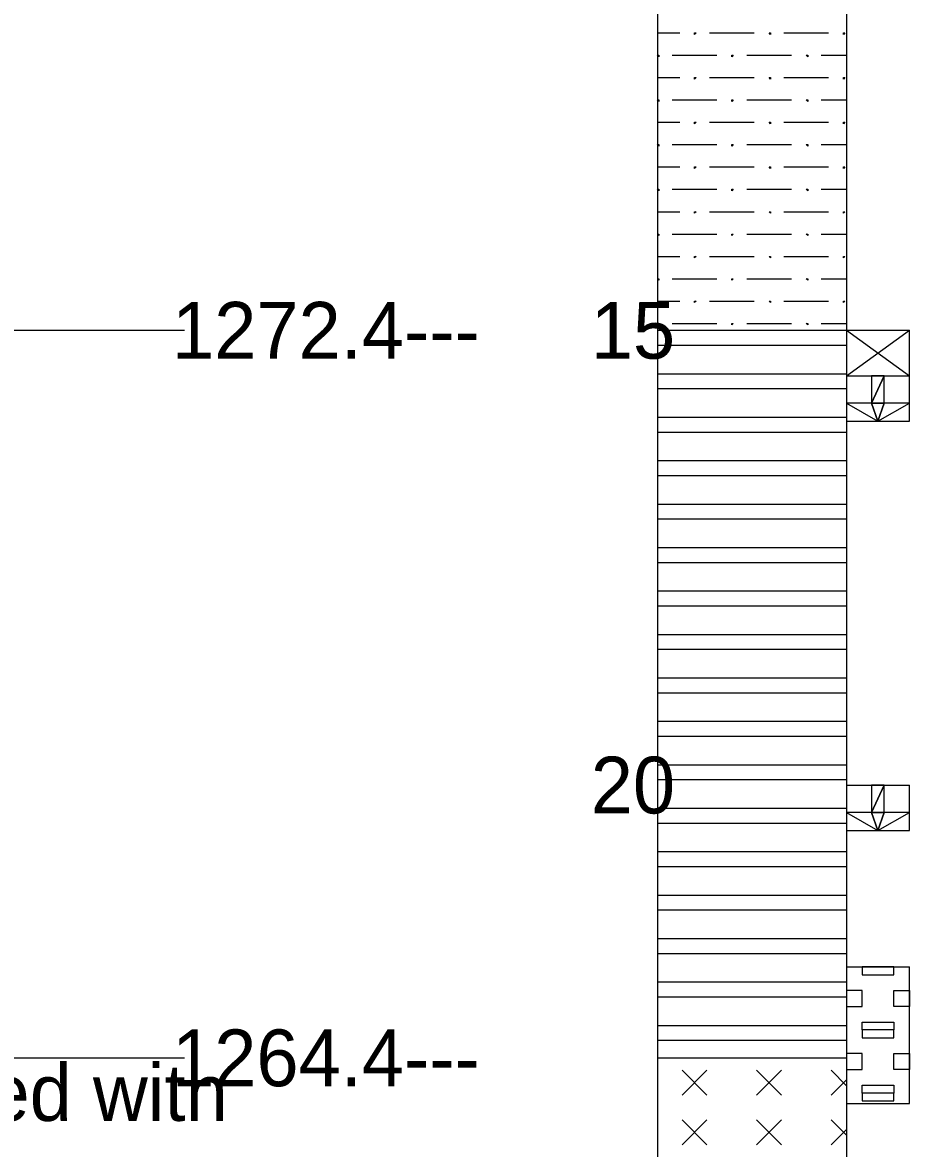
# Model space of a CAD drawing. Extents: x 2150148.6 to 2150220.1, y 143803.7 to 143875.1.
# Drawn here: x 2150200.808 to 2150203.153, y 143852.692 to 143855.669 of the extents above; entities that cross this region are included whole.
import ezdxf

# ---------------------------------------------------------------- set-up
doc = ezdxf.new("R2010")
doc.units = 0
doc.layers.add('Default', color=7, linetype='Continuous')

msp = doc.modelspace()

# ---------------------------------------------------------------- linework, layer by layer
at = {"layer": 'Default'}
for points in [[(2150202.4866, 143858.3678), (2150202.4866, 143846.4416)], [(2150202.9866, 143858.3606), (2150202.9866, 143846.4416)], [(2150202.4866, 143855.6411), (2150202.5456, 143855.6411)], [(2150202.585, 143855.6411), (2150202.5889, 143855.6411), (2150202.585, 143855.6372), (2150202.585, 143855.6411)], [(2150202.6244, 143855.6411), (2150202.7425, 143855.6411)], [(2150202.7818, 143855.6411), (2150202.7858, 143855.6411), (2150202.7858, 143855.6372), (2150202.7818, 143855.6411)], [(2150202.8212, 143855.6411), (2150202.8803, 143855.6411)], [(2150202.8803, 143855.6411), (2150202.9393, 143855.6411)], [(2150202.9787, 143855.6411), (2150202.9826, 143855.6411), (2150202.9787, 143855.6372), (2150202.9787, 143855.6411)], [(2150202.4866, 143855.5821), (2150202.4905, 143855.5821), (2150202.4905, 143855.5781), (2150202.4866, 143855.5821)], [(2150202.5259, 143855.5821), (2150202.644, 143855.5821)], [(2150202.6834, 143855.5821), (2150202.6874, 143855.5821), (2150202.6834, 143855.5781), (2150202.6834, 143855.5821)], [(2150202.7228, 143855.5821), (2150202.8409, 143855.5821)], [(2150202.8803, 143855.5821), (2150202.8842, 143855.5821), (2150202.8842, 143855.5781), (2150202.8803, 143855.5821)], [(2150202.9196, 143855.5821), (2150202.9866, 143855.5821)], [(2150202.4866, 143855.523), (2150202.5456, 143855.523)], [(2150202.585, 143855.523), (2150202.5889, 143855.523), (2150202.585, 143855.5191), (2150202.585, 143855.523)], [(2150202.6244, 143855.523), (2150202.7425, 143855.523)], [(2150202.7818, 143855.523), (2150202.7858, 143855.523), (2150202.7858, 143855.5191), (2150202.7818, 143855.523)], [(2150202.8212, 143855.523), (2150202.8803, 143855.523)], [(2150202.8803, 143855.523), (2150202.9393, 143855.523)], [(2150202.9787, 143855.523), (2150202.9826, 143855.523), (2150202.9787, 143855.5191), (2150202.9787, 143855.523)], [(2150202.4866, 143855.464), (2150202.4905, 143855.464), (2150202.4905, 143855.46), (2150202.4866, 143855.464)], [(2150202.5259, 143855.464), (2150202.644, 143855.464)], [(2150202.6834, 143855.464), (2150202.6874, 143855.464), (2150202.6834, 143855.46), (2150202.6834, 143855.464)], [(2150202.7228, 143855.464), (2150202.8409, 143855.464)], [(2150202.8803, 143855.464), (2150202.8842, 143855.464), (2150202.8842, 143855.46), (2150202.8803, 143855.464)], [(2150202.9196, 143855.464), (2150202.9866, 143855.464)], [(2150202.4866, 143855.4049), (2150202.5456, 143855.4049)], [(2150202.585, 143855.4049), (2150202.5889, 143855.4049), (2150202.585, 143855.401), (2150202.585, 143855.4049)], [(2150202.6244, 143855.4049), (2150202.7425, 143855.4049)], [(2150202.7818, 143855.4049), (2150202.7858, 143855.4049), (2150202.7858, 143855.401), (2150202.7818, 143855.4049)], [(2150202.8212, 143855.4049), (2150202.8803, 143855.4049)], [(2150202.8803, 143855.4049), (2150202.9393, 143855.4049)], [(2150202.9787, 143855.4049), (2150202.9826, 143855.4049), (2150202.9787, 143855.401), (2150202.9787, 143855.4049)], [(2150202.4866, 143855.3459), (2150202.4905, 143855.3459), (2150202.4905, 143855.3419), (2150202.4866, 143855.3459)], [(2150202.5259, 143855.3459), (2150202.644, 143855.3459)], [(2150202.6834, 143855.3459), (2150202.6874, 143855.3459), (2150202.6834, 143855.3419), (2150202.6834, 143855.3459)], [(2150202.7228, 143855.3459), (2150202.8409, 143855.3459)], [(2150202.8803, 143855.3459), (2150202.8842, 143855.3459), (2150202.8842, 143855.3419), (2150202.8803, 143855.3459)], [(2150202.9196, 143855.3459), (2150202.9866, 143855.3459)], [(2150202.4866, 143855.2868), (2150202.5456, 143855.2868)], [(2150202.585, 143855.2868), (2150202.5889, 143855.2868), (2150202.585, 143855.2829), (2150202.585, 143855.2868)], [(2150202.6244, 143855.2868), (2150202.7425, 143855.2868)], [(2150202.7818, 143855.2868), (2150202.7858, 143855.2868), (2150202.7858, 143855.2829), (2150202.7818, 143855.2868)], [(2150202.8212, 143855.2868), (2150202.8803, 143855.2868)], [(2150202.8803, 143855.2868), (2150202.9393, 143855.2868)], [(2150202.9787, 143855.2868), (2150202.9826, 143855.2868), (2150202.9787, 143855.2829), (2150202.9787, 143855.2868)], [(2150202.4866, 143855.2278), (2150202.4905, 143855.2278), (2150202.4905, 143855.2238), (2150202.4866, 143855.2278)], [(2150202.5259, 143855.2278), (2150202.644, 143855.2278)], [(2150202.6834, 143855.2278), (2150202.6874, 143855.2278), (2150202.6834, 143855.2238), (2150202.6834, 143855.2278)], [(2150202.7228, 143855.2278), (2150202.8409, 143855.2278)], [(2150202.8803, 143855.2278), (2150202.8842, 143855.2278), (2150202.8842, 143855.2238), (2150202.8803, 143855.2278)], [(2150202.9196, 143855.2278), (2150202.9866, 143855.2278)], [(2150202.4866, 143855.1687), (2150202.5456, 143855.1687)], [(2150202.585, 143855.1687), (2150202.5889, 143855.1687), (2150202.585, 143855.1648), (2150202.585, 143855.1687)], [(2150202.6244, 143855.1687), (2150202.7425, 143855.1687)], [(2150202.7818, 143855.1687), (2150202.7858, 143855.1687), (2150202.7858, 143855.1648), (2150202.7818, 143855.1687)], [(2150202.8212, 143855.1687), (2150202.8803, 143855.1687)], [(2150202.8803, 143855.1687), (2150202.9393, 143855.1687)], [(2150202.9787, 143855.1687), (2150202.9826, 143855.1687), (2150202.9787, 143855.1648), (2150202.9787, 143855.1687)], [(2150202.4866, 143855.1096), (2150202.4905, 143855.1096), (2150202.4905, 143855.1057), (2150202.4866, 143855.1096)], [(2150202.5259, 143855.1096), (2150202.644, 143855.1096)], [(2150202.6834, 143855.1096), (2150202.6874, 143855.1096), (2150202.6834, 143855.1057), (2150202.6834, 143855.1096)], [(2150202.7228, 143855.1096), (2150202.8409, 143855.1096)], [(2150202.8803, 143855.1096), (2150202.8842, 143855.1096), (2150202.8842, 143855.1057), (2150202.8803, 143855.1096)], [(2150202.9196, 143855.1096), (2150202.9866, 143855.1096)], [(2150202.4866, 143855.0506), (2150202.5456, 143855.0506)], [(2150202.585, 143855.0506), (2150202.5889, 143855.0506), (2150202.585, 143855.0467), (2150202.585, 143855.0506)], [(2150202.6244, 143855.0506), (2150202.7425, 143855.0506)], [(2150202.7818, 143855.0506), (2150202.7858, 143855.0506), (2150202.7858, 143855.0467), (2150202.7818, 143855.0506)], [(2150202.8212, 143855.0506), (2150202.8803, 143855.0506)], [(2150202.8803, 143855.0506), (2150202.9393, 143855.0506)], [(2150202.9787, 143855.0506), (2150202.9826, 143855.0506), (2150202.9787, 143855.0467), (2150202.9787, 143855.0506)], [(2150202.4866, 143854.9915), (2150202.4905, 143854.9915), (2150202.4905, 143854.9876), (2150202.4866, 143854.9915)], [(2150202.5259, 143854.9915), (2150202.644, 143854.9915)], [(2150202.6834, 143854.9915), (2150202.6874, 143854.9915), (2150202.6834, 143854.9876), (2150202.6834, 143854.9915)], [(2150202.7228, 143854.9915), (2150202.8409, 143854.9915)], [(2150202.8803, 143854.9915), (2150202.8842, 143854.9915), (2150202.8842, 143854.9876), (2150202.8803, 143854.9915)], [(2150202.9196, 143854.9915), (2150202.9866, 143854.9915)], [(2150202.4866, 143854.9325), (2150202.5456, 143854.9325)], [(2150202.585, 143854.9325), (2150202.5889, 143854.9325), (2150202.585, 143854.9285), (2150202.585, 143854.9325)], [(2150202.6244, 143854.9325), (2150202.7425, 143854.9325)], [(2150202.7818, 143854.9325), (2150202.7858, 143854.9325), (2150202.7858, 143854.9285), (2150202.7818, 143854.9325)], [(2150202.8212, 143854.9325), (2150202.8803, 143854.9325)], [(2150202.8803, 143854.9325), (2150202.9393, 143854.9325)], [(2150202.9787, 143854.9325), (2150202.9826, 143854.9325), (2150202.9787, 143854.9285), (2150202.9787, 143854.9325)], [(2150197.0699, 143854.8551), (2150201.2366, 143854.8551)], [(2150202.4866, 143854.8734), (2150202.4905, 143854.8734), (2150202.4905, 143854.8695), (2150202.4866, 143854.8734)], [(2150202.4866, 143854.8551), (2150202.9866, 143854.8551)], [(2150202.4866, 143854.8551), (2150202.9866, 143854.8551)], [(2150202.5259, 143854.8734), (2150202.644, 143854.8734)], [(2150202.6834, 143854.8734), (2150202.6874, 143854.8734), (2150202.6834, 143854.8695), (2150202.6834, 143854.8734)], [(2150202.7228, 143854.8734), (2150202.8409, 143854.8734)], [(2150202.8803, 143854.8734), (2150202.8842, 143854.8734), (2150202.8842, 143854.8695), (2150202.8803, 143854.8734)], [(2150202.9196, 143854.8734), (2150202.9866, 143854.8734)], [(2150202.9866, 143854.8551), (2150203.1532, 143854.7349)], [(2150202.9866, 143854.7349), (2150203.1532, 143854.8551)], [(2150202.9866, 143854.8551), (2150203.1532, 143854.8551)], [(2150203.1532, 143854.7349), (2150203.1532, 143854.8551)], [(2150202.4866, 143854.8157), (2150202.9866, 143854.8157)], [(2150202.4866, 143854.7402), (2150202.9866, 143854.7402)], [(2150202.9866, 143854.7349), (2150203.1532, 143854.7349)], [(2150202.9866, 143854.7349), (2150203.1532, 143854.7349)], [(2150203.1532, 143854.6147), (2150203.1532, 143854.7349)], [(2150202.4866, 143854.7009), (2150202.9866, 143854.7009)], [(2150202.4866, 143854.6254), (2150202.9866, 143854.6254)], [(2150202.9866, 143854.6147), (2150203.1532, 143854.6147)], [(2150202.4866, 143854.586), (2150202.9866, 143854.586)], [(2150202.4866, 143854.5106), (2150202.9866, 143854.5106)], [(2150202.4866, 143854.4712), (2150202.9866, 143854.4712)], [(2150202.4866, 143854.3957), (2150202.9866, 143854.3957)], [(2150202.4866, 143854.3564), (2150202.9866, 143854.3564)], [(2150202.4866, 143854.2809), (2150202.9866, 143854.2809)], [(2150202.4866, 143854.2415), (2150202.9866, 143854.2415)], [(2150202.4866, 143854.1661), (2150202.9866, 143854.1661)], [(2150202.4866, 143854.1267), (2150202.9866, 143854.1267)], [(2150202.4866, 143854.0513), (2150202.9866, 143854.0513)], [(2150202.4866, 143854.0119), (2150202.9866, 143854.0119)], [(2150202.4866, 143853.9364), (2150202.9866, 143853.9364)], [(2150202.4866, 143853.8971), (2150202.9866, 143853.8971)], [(2150202.4866, 143853.8216), (2150202.9866, 143853.8216)], [(2150202.4866, 143853.7822), (2150202.9866, 143853.7822)], [(2150202.4866, 143853.7068), (2150202.9866, 143853.7068)], [(2150202.4866, 143853.6674), (2150202.9866, 143853.6674)], [(2150202.9866, 143853.6531), (2150203.1532, 143853.6531)], [(2150203.1532, 143853.533), (2150203.1532, 143853.6531)], [(2150202.4866, 143853.5919), (2150202.9866, 143853.5919)], [(2150202.4866, 143853.5526), (2150202.9866, 143853.5526)], [(2150202.9866, 143853.533), (2150203.1532, 143853.533)], [(2150202.4866, 143853.4771), (2150202.9866, 143853.4771)], [(2150202.4866, 143853.4377), (2150202.9866, 143853.4377)], [(2150202.4866, 143853.3623), (2150202.9866, 143853.3623)], [(2150202.4866, 143853.3229), (2150202.9866, 143853.3229)], [(2150202.4866, 143853.2475), (2150202.9866, 143853.2475)], [(2150202.4866, 143853.2081), (2150202.9866, 143853.2081)], [(2150202.9866, 143853.1724), (2150203.1532, 143853.1724)], [(2150203.1532, 143852.8118), (2150203.1532, 143853.1724)], [(2150202.4866, 143853.1326), (2150202.9866, 143853.1326)], [(2150202.4866, 143853.0933), (2150202.9866, 143853.0933)], [(2150202.4866, 143853.0178), (2150202.9866, 143853.0178)], [(2150202.4866, 143852.9784), (2150202.9866, 143852.9784)], [(2150197.0699, 143852.932), (2150201.2366, 143852.932)], [(2150202.4866, 143852.932), (2150202.9866, 143852.932)], [(2150202.6178, 143852.8992), (2150202.5522, 143852.8336)], [(2150202.5522, 143852.8992), (2150202.6178, 143852.8336)], [(2150202.8147, 143852.8992), (2150202.749, 143852.8336)], [(2150202.749, 143852.8992), (2150202.8147, 143852.8336)], [(2150202.9459, 143852.8992), (2150202.9866, 143852.8585)], [(2150202.9866, 143852.8742), (2150202.9459, 143852.8336)], [(2150202.9866, 143852.8118), (2150203.1532, 143852.8118)], [(2150202.6178, 143852.7679), (2150202.5522, 143852.7023)], [(2150202.5522, 143852.7679), (2150202.6178, 143852.7023)], [(2150202.8147, 143852.7679), (2150202.749, 143852.7023)], [(2150202.749, 143852.7679), (2150202.8147, 143852.7023)], [(2150202.9459, 143852.7679), (2150202.9866, 143852.7273)], [(2150202.9866, 143852.743), (2150202.9459, 143852.7023)]]:
    msp.add_lwpolyline(points, dxfattribs=at)
for points in [[(2150203.0532, 143854.6628), (2150203.0866, 143854.6628), (2150203.0866, 143854.7349), (2150203.0532, 143854.6628)], [(2150203.0532, 143854.6628), (2150203.0866, 143854.7349), (2150203.0532, 143854.7349), (2150203.0532, 143854.6628)], [(2150203.0532, 143854.6628), (2150202.9866, 143854.6628), (2150203.0699, 143854.6147), (2150203.0532, 143854.6628)], [(2150203.0532, 143854.6628), (2150203.0699, 143854.6147), (2150203.0866, 143854.6628), (2150203.0532, 143854.6628)], [(2150203.0699, 143854.6147), (2150203.1532, 143854.6628), (2150203.0866, 143854.6628), (2150203.0699, 143854.6147)], [(2150203.0532, 143853.581), (2150203.0866, 143853.581), (2150203.0866, 143853.6531), (2150203.0532, 143853.581)], [(2150203.0532, 143853.581), (2150203.0866, 143853.6531), (2150203.0532, 143853.6531), (2150203.0532, 143853.581)], [(2150203.0532, 143853.581), (2150202.9866, 143853.581), (2150203.0699, 143853.533), (2150203.0532, 143853.581)], [(2150203.0532, 143853.581), (2150203.0699, 143853.533), (2150203.0866, 143853.581), (2150203.0532, 143853.581)], [(2150203.0699, 143853.533), (2150203.1532, 143853.581), (2150203.0866, 143853.581), (2150203.0699, 143853.533)], [(2150203.0282, 143853.1724), (2150203.0282, 143853.1515), (2150203.1116, 143853.1515), (2150203.1116, 143853.1724)], [(2150202.9866, 143853.0682), (2150203.0282, 143853.0682), (2150203.0282, 143853.1099), (2150202.9866, 143853.1099)], [(2150203.1532, 143853.0682), (2150203.1116, 143853.0682), (2150203.1116, 143853.1099), (2150203.1532, 143853.1099)], [(2150203.0282, 143853.0057), (2150203.0282, 143853.0265), (2150203.1116, 143853.0265), (2150203.1116, 143853.0057)], [(2150203.0282, 143853.0057), (2150203.0282, 143852.9849), (2150203.1116, 143852.9849), (2150203.1116, 143853.0057)], [(2150202.9866, 143852.9015), (2150203.0282, 143852.9015), (2150203.0282, 143852.9432), (2150202.9866, 143852.9432)], [(2150203.1532, 143852.9015), (2150203.1116, 143852.9015), (2150203.1116, 143852.9432), (2150203.1532, 143852.9432)], [(2150203.0282, 143852.839), (2150203.0282, 143852.8599), (2150203.1116, 143852.8599), (2150203.1116, 143852.839)], [(2150203.0282, 143852.839), (2150203.0282, 143852.8182), (2150203.1116, 143852.8182), (2150203.1116, 143852.839)]]:
    msp.add_lwpolyline(points, close=True, dxfattribs=at)

# ---------------------------------------------------------------- texts
for s, p in [('1272.4---', (2150201.2032, 143854.7801)), ('15', (2150202.3104, 143854.7801)), ('20', (2150202.3104, 143853.5781)), ('1264.4---', (2150201.2032, 143852.857)), ('SILTSTONE, Shaley, hard to very hard, red with', (2150197.0699, 143852.7653))]:
    msp.add_text(s, height=0.15, dxfattribs=at).set_placement(p)

doc.saveas('drawing.dxf')
